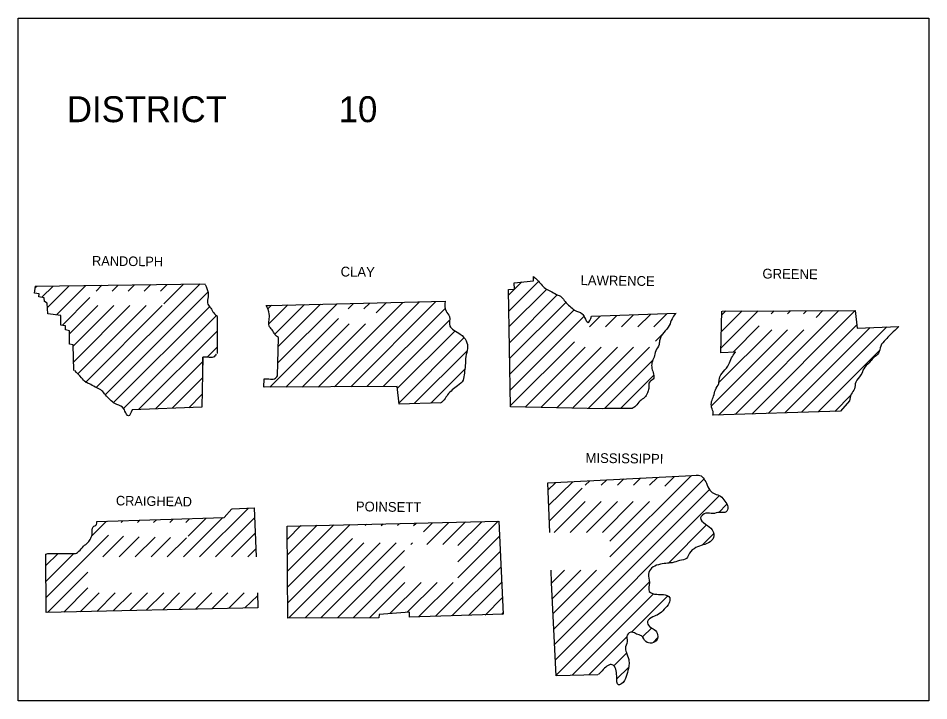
# Model space of a CAD drawing. Extents: x 21307 to 29830, y 1322443 to 1332359.
# Drawn here: x 27792.5 to 28192.5, y 1325389.6 to 1325689.6 of the extents above; entities that cross this region are included whole.
import ezdxf

# ---------------------------------------------------------------- set-up
doc = ezdxf.new("R2010")
doc.units = 0
doc.layers.add('R_Draft', color=7, linetype='Continuous')

msp = doc.modelspace()

# ---------------------------------------------------------------- linework, layer by layer
at = {"layer": 'R_Draft'}
msp.add_lwpolyline([(27792.46, 1325389.62), (27792.46, 1325689.62), (28192.46, 1325689.62), (28192.46, 1325389.62)], close=True, dxfattribs=at)
for points in [[(28049.06, 1325517.92), (28008.76, 1325518.82), (28007.86, 1325570.42), (28010.46, 1325570.52), (28010.36, 1325573.32), (28018.86, 1325574.12), (28018.86, 1325576.12)], [(27799.96, 1325571.82), (27874.56, 1325572.92)], [(27805.36, 1325562.42), (27814.86, 1325572.02)], [(27809.26, 1325559.22), (27822.06, 1325572.02)], [(27826.76, 1325527.32), (27872.36, 1325572.82)], [(27826.76, 1325569.62), (27829.26, 1325572.22)], [(27833.76, 1325569.62), (27836.36, 1325572.32)], [(27840.76, 1325569.62), (27843.56, 1325572.42)], [(27847.86, 1325569.62), (27850.76, 1325572.52)], [(27854.96, 1325569.62), (27857.96, 1325572.62)], [(27856.46, 1325564.12), (27865.06, 1325572.72)], [(28007.86, 1325567.92), (28010.46, 1325570.52), (28013.66, 1325573.72)], [(28008.06, 1325561.02), (28020.96, 1325573.92)], [(27816.96, 1325534.72), (27816.56, 1325546.12), (27814.96, 1325546.42), (27815.06, 1325552.22), (27813.26, 1325552.72), (27813.26, 1325554.42), (27811.16, 1325554.72), (27811.16, 1325559.02), (27805.46, 1325559.62), (27805.16, 1325564.42), (27804.06, 1325565.12), (27803.86, 1325566.72), (27801.56, 1325567.22), (27801.66, 1325568.42), (27799.66, 1325568.72), (27800.06, 1325571.82)], [(27799.96, 1325571.22), (27800.66, 1325571.82)], [(27802.86, 1325567.02), (27807.76, 1325571.92)], [(27830.76, 1325524.22), (27875.76, 1325569.22)], [(28008.16, 1325554.12), (28024.46, 1325570.42)], [(28008.36, 1325547.12), (28029.16, 1325568.02)], [(27811.76, 1325554.62), (27823.86, 1325566.82)], [(27901.36, 1325563.42), (27902.36, 1325563.42), (27979.96, 1325565.22)], [(27906.56, 1325538.12), (27932.56, 1325564.12)], [(27924.26, 1325527.52), (27961.46, 1325564.72)], [(27931.46, 1325527.62), (27968.76, 1325564.92)], [(27937.36, 1325561.82), (27939.76, 1325564.22)], [(27938.56, 1325527.62), (27975.96, 1325565.12)], [(27944.36, 1325561.82), (27946.96, 1325564.42)], [(27949.76, 1325560.12), (27954.26, 1325564.62)], [(28008.46, 1325540.22), (28032.96, 1325564.72)], [(27815.06, 1325550.92), (27827.46, 1325563.32)], [(27816.66, 1325545.52), (27834.46, 1325563.32)], [(27816.86, 1325538.62), (27841.56, 1325563.32)], [(27818.76, 1325533.42), (27848.66, 1325563.32)], [(27822.06, 1325529.62), (27822.16, 1325529.72), (27855.76, 1325563.32)], [(27834.46, 1325520.82), (27876.46, 1325562.82)], [(27902.06, 1325561.82), (27903.66, 1325563.52)], [(27902.66, 1325555.42), (27910.86, 1325563.62)], [(27905.16, 1325550.82), (27918.16, 1325563.82)], [(27906.66, 1325545.32), (27925.26, 1325563.92)], [(27945.66, 1325527.72), (27980.16, 1325562.22)], [(28008.56, 1325533.32), (28036.66, 1325561.42)], [(28101.16, 1325544.62), (28117.56, 1325561.02)], [(28101.16, 1325542.62), (28101.56, 1325560.92)], [(28101.36, 1325551.92), (28110.46, 1325561.02)], [(28101.56, 1325559.22), (28103.36, 1325561.02)], [(28101.66, 1325560.92), (28160.16, 1325561.22), (28160.96, 1325553.42), (28179.26, 1325554.12)], [(28107.36, 1325515.42), (28152.96, 1325561.12)], [(28114.66, 1325515.62), (28160.16, 1325561.22)], [(28123.26, 1325559.62), (28124.56, 1325561.02)], [(28130.36, 1325559.62), (28131.76, 1325561.02)], [(28137.36, 1325559.62), (28138.76, 1325561.02)], [(28142.96, 1325558.12), (28145.96, 1325561.12)], [(27838.76, 1325518.12), (27879.56, 1325558.92)], [(27879.86, 1325558.52), (27879.86, 1325542.22)], [(27903.06, 1325527.52), (27933.16, 1325557.62)], [(27952.76, 1325527.72), (27981.76, 1325556.72)], [(28008.66, 1325526.32), (28040.96, 1325558.52)], [(28043.36, 1325553.92), (28048.16, 1325558.72)], [(28044.36, 1325558.62), (28081.46, 1325559.92)], [(28050.46, 1325553.92), (28055.46, 1325559.02)], [(28057.46, 1325553.92), (28062.76, 1325559.22)], [(28064.66, 1325553.92), (28070.16, 1325559.42)], [(28071.66, 1325553.92), (28077.46, 1325559.72)], [(27845.46, 1325517.72), (27879.86, 1325552.12)], [(27910.06, 1325527.52), (27937.86, 1325555.32)], [(27917.26, 1325527.52), (27945.06, 1325555.32)], [(27959.06, 1325527.02), (27984.26, 1325552.12)], [(28097.06, 1325519.32), (28130.46, 1325552.72)], [(28100.06, 1325515.22), (28137.56, 1325552.72)], [(28100.36, 1325529.72), (28123.46, 1325552.72)], [(28106.46, 1325542.82), (28117.96, 1325554.42)], [(28121.96, 1325515.92), (28160.76, 1325554.72)], [(28129.26, 1325516.12), (28166.76, 1325553.62)], [(28136.56, 1325516.42), (28174.06, 1325553.92)], [(27906.36, 1325532.42), (27906.76, 1325549.22)], [(27959.76, 1325520.62), (27988.26, 1325549.12)], [(28072.46, 1325547.72), (28075.66, 1325550.92)], [(27875.46, 1325540.62), (27879.86, 1325545.02)], [(28008.76, 1325519.42), (28036.76, 1325547.42)], [(28015.16, 1325518.62), (28041.56, 1325545.02)], [(28022.06, 1325518.52), (28048.56, 1325545.02)], [(28029.06, 1325518.42), (28055.76, 1325545.02)], [(28035.96, 1325518.22), (28062.76, 1325545.02)], [(28042.86, 1325518.12), (28069.76, 1325545.02)], [(27873.56, 1325536.92), (27873.56, 1325540.62), (27873.06, 1325518.62)], [(27966.46, 1325520.22), (27989.56, 1325543.32)], [(28107.66, 1325542.82), (28101.16, 1325542.62)], [(28143.86, 1325516.62), (28170.66, 1325543.42)], [(27852.76, 1325517.92), (27873.56, 1325538.72), (27873.56, 1325538.72)], [(28049.96, 1325518.12), (28071.06, 1325539.22)], [(27973.76, 1325520.42), (27988.66, 1325535.32)], [(28057.06, 1325518.12), (28071.56, 1325532.62)], [(27860.06, 1325518.22), (27873.36, 1325531.52)], [(27900.36, 1325527.42), (27900.46, 1325531.12)], [(27867.36, 1325518.42), (27873.16, 1325524.22)], [(27978.16, 1325520.62), (27959.76, 1325519.92), (27958.96, 1325527.72), (27900.46, 1325527.42)], [(28157.66, 1325521.52), (28153.66, 1325516.92), (28097.66, 1325515.12)], [(28151.16, 1325516.82), (28158.26, 1325523.92)], [(27873.06, 1325518.62), (27842.46, 1325517.52)], [(28062.16, 1325518.12), (28049.96, 1325518.12), (28049.06, 1325517.92)], [(28025.06, 1325485.42), (28091.36, 1325488.82)], [(28052.36, 1325452.82), (28088.16, 1325488.62)], [(28076.46, 1325483.92), (28080.76, 1325488.22)], [(28025.96, 1325463.62), (28025.06, 1325485.42)], [(28025.16, 1325482.22), (28028.56, 1325485.62)], [(28025.46, 1325475.42), (28036.06, 1325485.92)], [(28027.76, 1325421.12), (28093.56, 1325486.92), (28093.66, 1325487.02)], [(28041.56, 1325484.32), (28043.56, 1325486.32)], [(28048.56, 1325484.32), (28050.96, 1325486.72)], [(28055.66, 1325484.32), (28058.46, 1325487.12)], [(28062.76, 1325484.32), (28065.86, 1325487.52)], [(28069.76, 1325484.32), (28073.26, 1325487.82)], [(28025.76, 1325468.62), (28040.16, 1325483.02)], [(28028.06, 1325414.32), (28096.16, 1325482.42)], [(28027.86, 1325463.62), (28041.46, 1325477.22)], [(28028.46, 1325407.62), (28100.56, 1325479.82)], [(28034.96, 1325463.62), (28048.56, 1325477.22)], [(28042.06, 1325463.62), (28055.66, 1325477.22)], [(28049.06, 1325463.62), (28062.66, 1325477.22)], [(28052.36, 1325459.82), (28069.76, 1325477.22)], [(27826.96, 1325468.42), (27882.96, 1325470.22), (27886.26, 1325474.02)], [(27872.16, 1325452.82), (27893.56, 1325474.22)], [(27886.46, 1325473.92), (27896.06, 1325474.42)], [(27896.06, 1325474.42), (27896.96, 1325452.82)], [(28100.26, 1325472.32), (28103.66, 1325475.82)], [(27824.76, 1325462.12), (27831.26, 1325468.52)], [(27837.76, 1325468.02), (27838.46, 1325468.72)], [(27844.86, 1325468.02), (27845.76, 1325468.92)], [(27851.96, 1325468.02), (27853.16, 1325469.22)], [(27859.06, 1325468.02), (27860.46, 1325469.42)], [(27865.06, 1325452.82), (27882.36, 1325470.12)], [(27866.06, 1325468.02), (27867.66, 1325469.62)], [(27867.16, 1325462.02), (27875.06, 1325469.92)], [(27879.16, 1325452.82), (27896.16, 1325469.92)], [(27910.66, 1325466.42), (28003.56, 1325468.52)], [(27971.96, 1325458.32), (27981.66, 1325468.02)], [(27979.06, 1325458.32), (27988.96, 1325468.22)], [(27985.56, 1325450.72), (28003.36, 1325468.52)], [(27985.56, 1325457.82), (27996.16, 1325468.32)], [(28003.56, 1325468.52), (28005.56, 1325427.62)], [(27910.96, 1325425.92), (27910.66, 1325466.42)], [(27910.76, 1325453.72), (27923.86, 1325466.82)], [(27910.76, 1325460.72), (27916.56, 1325466.62)], [(27910.86, 1325446.72), (27931.06, 1325466.92)], [(27910.96, 1325439.72), (27938.26, 1325467.12)], [(27944.86, 1325466.62), (27945.46, 1325467.22)], [(27951.96, 1325466.62), (27952.76, 1325467.42)], [(27959.06, 1325466.62), (27959.96, 1325467.52)], [(27966.16, 1325466.62), (27967.26, 1325467.72)], [(27970.46, 1325463.82), (27974.46, 1325467.82)], [(28078.06, 1325450.12), (28094.76, 1325466.92)], [(27804.76, 1325435.02), (27832.16, 1325462.42)], [(27829.66, 1325452.82), (27838.76, 1325461.92)], [(27836.76, 1325452.82), (27845.66, 1325461.72)], [(27843.86, 1325452.82), (27852.56, 1325461.52)], [(27850.86, 1325452.82), (27859.36, 1325461.32)], [(27857.96, 1325452.82), (27866.36, 1325461.22)], [(27886.16, 1325452.82), (27896.46, 1325463.12)], [(27910.96, 1325432.72), (27939.26, 1325461.02)], [(27985.56, 1325443.72), (28003.86, 1325461.92)], [(28092.96, 1325458.02), (28097.96, 1325463.02)], [(27893.26, 1325452.82), (27896.66, 1325456.22)], [(27911.36, 1325426.02), (27944.36, 1325459.02)], [(27918.46, 1325426.02), (27951.46, 1325459.02)], [(27925.46, 1325426.02), (27958.56, 1325459.02)], [(27964.96, 1325458.32), (27965.66, 1325459.02)], [(27804.56, 1325454.12), (27805.46, 1325454.32), (27817.66, 1325454.32)], [(27804.76, 1325428.42), (27804.56, 1325454.12)], [(27804.66, 1325442.02), (27816.96, 1325454.32)], [(27804.66, 1325449.02), (27809.96, 1325454.32)], [(27932.66, 1325426.12), (27962.16, 1325455.62)], [(27975.76, 1325426.82), (28004.16, 1325455.22)], [(27939.66, 1325426.12), (27962.16, 1325448.62)], [(27982.96, 1325426.92), (28004.56, 1325448.52)], [(27805.26, 1325428.42), (27823.06, 1325446.22)], [(28028.76, 1325400.62), (28026.76, 1325441.52), (28026.56, 1325447.02)], [(28026.86, 1325441.42), (28032.46, 1325447.02)], [(28027.16, 1325434.62), (28039.56, 1325447.02)], [(28027.46, 1325427.92), (28046.56, 1325447.02)], [(27946.76, 1325426.12), (27962.36, 1325441.62)], [(27955.66, 1325427.92), (27969.46, 1325441.62)], [(27963.36, 1325428.52), (27976.46, 1325441.62)], [(27968.46, 1325426.62), (27983.56, 1325441.62)], [(27990.26, 1325427.12), (28004.86, 1325441.72)], [(28028.76, 1325400.82), (28069.66, 1325441.82)], [(27812.46, 1325428.62), (27823.06, 1325439.22)], [(27819.66, 1325428.72), (27828.06, 1325437.02)], [(27826.96, 1325428.92), (27835.06, 1325437.02)], [(27834.16, 1325429.12), (27842.16, 1325437.02)], [(27841.46, 1325429.32), (27849.26, 1325437.02)], [(27848.66, 1325429.42), (27856.36, 1325437.02)], [(27855.96, 1325429.62), (27863.36, 1325437.02)], [(27863.16, 1325429.82), (27870.36, 1325437.02)], [(27870.36, 1325429.92), (27877.46, 1325437.02)], [(27877.56, 1325430.02), (27884.56, 1325437.02)], [(27884.86, 1325430.22), (27891.66, 1325437.02)], [(27897.56, 1325437.02), (27897.76, 1325430.52)], [(28035.76, 1325400.82), (28071.56, 1325436.62)], [(27892.06, 1325430.42), (27897.56, 1325435.82)], [(27997.56, 1325427.32), (28005.16, 1325435.02)], [(28061.96, 1325419.92), (28077.76, 1325435.72)], [(27897.76, 1325430.52), (27804.76, 1325428.42)], [(28005.56, 1325427.62), (27964.36, 1325426.42), (27964.36, 1325428.52), (27950.96, 1325427.52), (27950.86, 1325426.12), (27910.96, 1325425.92)], [(28004.86, 1325427.52), (28005.56, 1325428.22)], [(28066.76, 1325417.72), (28070.86, 1325421.72)], [(28043.06, 1325401.02), (28059.96, 1325417.92)], [(28071.36, 1325415.22), (28073.36, 1325417.22)], [(28054.16, 1325405.02), (28059.76, 1325410.72)], [(28055.36, 1325399.22), (28060.66, 1325404.42)], [(28047.06, 1325401.02), (28028.76, 1325400.62)]]:
    msp.add_lwpolyline(points, dxfattribs=at)
for points in [[(28018.86, 1325576.12), (28022.16, 1325572.72), (28024.06, 1325570.82), (28026.26, 1325569.72), (28028.86, 1325568.22), (28031.16, 1325567.02), (28032.66, 1325565.12), (28034.76, 1325563.02), (28036.86, 1325561.32), (28040.16, 1325559.72), (28041.26, 1325558.02), (28042.76, 1325555.92), (28044.36, 1325558.62)], [(27874.56, 1325572.62), (27875.86, 1325569.12), (27875.76, 1325566.42), (27875.76, 1325563.92), (27877.06, 1325562.22), (27878.36, 1325560.12), (27880.06, 1325558.62)], [(27979.96, 1325565.22), (27980.46, 1325560.82), (27981.86, 1325558.52), (27982.06, 1325554.32), (27983.76, 1325552.52), (27986.66, 1325550.72), (27989.26, 1325547.82), (27989.86, 1325544.42), (27989.06, 1325540.92), (27988.86, 1325537.02), (27988.46, 1325533.62), (27987.86, 1325530.52), (27985.46, 1325528.02), (27983.16, 1325526.22), (27981.06, 1325524.12), (27979.56, 1325521.92), (27977.96, 1325520.42)], [(27979.96, 1325565.22), (27980.46, 1325560.82), (27981.86, 1325558.52), (27982.06, 1325554.32), (27983.76, 1325552.52), (27986.66, 1325550.72), (27989.26, 1325547.82), (27989.86, 1325544.42), (27989.06, 1325540.92), (27988.86, 1325537.02), (27988.46, 1325533.62), (27987.86, 1325530.52), (27985.46, 1325528.02), (27983.16, 1325526.22), (27981.06, 1325524.12), (27979.56, 1325521.92), (27977.96, 1325520.42)], [(27906.76, 1325549.22), (27905.26, 1325550.62), (27903.96, 1325552.72), (27902.66, 1325554.42), (27902.66, 1325556.92), (27902.76, 1325559.62), (27901.36, 1325563.42)], [(28081.16, 1325559.82), (28079.66, 1325557.42), (28078.46, 1325554.62), (28076.06, 1325551.42), (28074.26, 1325548.32), (28073.96, 1325546.22), (28072.56, 1325543.42), (28071.76, 1325540.62), (28070.86, 1325538.22), (28070.86, 1325535.72), (28071.56, 1325533.22), (28071.36, 1325530.92), (28069.86, 1325529.82), (28069.46, 1325526.92), (28068.86, 1325524.92), (28067.56, 1325522.92), (28065.66, 1325521.42), (28063.66, 1325519.12), (28062.16, 1325518.12)], [(28179.26, 1325554.12), (28178.16, 1325553.02), (28175.56, 1325550.52), (28173.46, 1325548.32), (28171.36, 1325545.52), (28170.36, 1325542.42), (28168.06, 1325540.22), (28166.26, 1325538.22), (28163.86, 1325535.52), (28162.66, 1325532.82), (28160.36, 1325529.72), (28159.86, 1325526.72), (28158.36, 1325524.32), (28157.66, 1325521.52)], [(28179.26, 1325554.12), (28178.16, 1325553.02), (28175.56, 1325550.52), (28173.46, 1325548.32), (28171.36, 1325545.52), (28170.36, 1325542.42), (28168.06, 1325540.22), (28166.26, 1325538.22), (28163.86, 1325535.52), (28162.66, 1325532.82), (28160.36, 1325529.72), (28159.86, 1325526.72), (28158.36, 1325524.32), (28157.66, 1325521.52)], [(27879.46, 1325541.92), (27878.16, 1325540.62), (27875.66, 1325540.62), (27873.56, 1325540.62)], [(28097.66, 1325515.12), (28097.76, 1325516.12), (28097.06, 1325518.62), (28097.06, 1325521.12), (28097.96, 1325523.52), (28098.76, 1325526.32), (28100.16, 1325529.12), (28100.46, 1325531.22), (28102.26, 1325534.32), (28104.66, 1325537.52), (28105.86, 1325540.32), (28107.36, 1325542.72)], [(27842.46, 1325517.52), (27840.86, 1325514.82), (27839.36, 1325516.92), (27838.26, 1325518.62), (27834.96, 1325520.22), (27832.86, 1325521.92), (27830.76, 1325524.02), (27829.26, 1325525.92), (27826.96, 1325527.12), (27824.36, 1325528.62), (27822.16, 1325529.72), (27820.26, 1325531.62), (27817.36, 1325534.72)], [(27900.46, 1325531.12), (27902.56, 1325531.12), (27905.06, 1325531.12), (27906.36, 1325532.42)], [(28090.26, 1325488.72), (28091.36, 1325488.82), (28094.76, 1325485.22), (28096.26, 1325482.22), (28098.46, 1325480.52), (28100.96, 1325479.62), (28102.86, 1325477.32), (28104.16, 1325474.82), (28103.46, 1325472.62), (28100.66, 1325472.42), (28097.56, 1325471.92), (28094.56, 1325472.02), (28092.16, 1325470.02), (28094.36, 1325467.32), (28097.26, 1325464.82), (28098.06, 1325462.12), (28096.46, 1325459.52), (28093.26, 1325458.12), (28090.16, 1325456.92), (28087.36, 1325454.52), (28086.06, 1325452.22), (28082.96, 1325451.22), (28079.76, 1325450.32), (28076.96, 1325450.02), (28073.76, 1325449.42), (28070.66, 1325447.92), (28069.36, 1325445.32), (28069.76, 1325441.62), (28069.66, 1325437.72), (28072.96, 1325436.42), (28075.86, 1325436.32), (28078.66, 1325434.82), (28078.36, 1325432.62), (28076.26, 1325429.82), (28073.76, 1325427.62), (28071.26, 1325426.52), (28068.96, 1325424.42), (28069.76, 1325422.32), (28071.86, 1325420.92), (28073.36, 1325418.62), (28073.16, 1325416.52), (28070.76, 1325415.02), (28068.16, 1325415.62), (28066.26, 1325418.12), (28064.06, 1325418.92), (28062.16, 1325419.82), (28059.96, 1325418.52), (28059.96, 1325415.62), (28059.16, 1325412.52), (28059.86, 1325410.22), (28060.76, 1325407.02), (28060.66, 1325404.62), (28059.86, 1325401.22), (28058.16, 1325397.72), (28056.16, 1325396.62), (28055.36, 1325400.42), (28054.96, 1325403.52), (28053.76, 1325405.32), (28052.16, 1325405.42), (28050.06, 1325403.92), (28047.76, 1325401.62), (28047.16, 1325401.12)], [(28090.26, 1325488.72), (28091.36, 1325488.82), (28094.76, 1325485.22), (28096.26, 1325482.22), (28098.46, 1325480.52), (28100.96, 1325479.62), (28102.86, 1325477.32), (28104.16, 1325474.82), (28103.46, 1325472.62), (28100.66, 1325472.42), (28097.56, 1325471.92), (28094.56, 1325472.02), (28092.16, 1325470.02), (28094.36, 1325467.32), (28097.26, 1325464.82), (28098.06, 1325462.12), (28096.46, 1325459.52), (28093.26, 1325458.12), (28090.16, 1325456.92), (28087.36, 1325454.52), (28086.06, 1325452.22), (28082.96, 1325451.22), (28079.76, 1325450.32), (28076.96, 1325450.02), (28073.76, 1325449.42), (28070.66, 1325447.92), (28069.36, 1325445.32), (28069.76, 1325441.62), (28069.66, 1325437.72), (28072.96, 1325436.42), (28075.86, 1325436.32), (28078.66, 1325434.82), (28078.36, 1325432.62), (28076.26, 1325429.82), (28073.76, 1325427.62), (28071.26, 1325426.52), (28068.96, 1325424.42), (28069.76, 1325422.32), (28071.86, 1325420.92), (28073.36, 1325418.62), (28073.16, 1325416.52), (28070.76, 1325415.02), (28068.16, 1325415.62), (28066.26, 1325418.12), (28064.06, 1325418.92), (28062.16, 1325419.82), (28059.96, 1325418.52), (28059.96, 1325415.62), (28059.16, 1325412.52), (28059.86, 1325410.22), (28060.76, 1325407.02), (28060.66, 1325404.62), (28059.86, 1325401.22), (28058.16, 1325397.72), (28056.16, 1325396.62), (28055.36, 1325400.42), (28054.96, 1325403.52), (28053.76, 1325405.32), (28052.16, 1325405.42), (28050.06, 1325403.92), (28047.76, 1325401.62), (28047.16, 1325401.12)], [(27817.66, 1325454.32), (27819.16, 1325455.32), (27821.16, 1325457.62), (27823.06, 1325459.12), (27824.36, 1325461.12), (27824.96, 1325463.12), (27825.36, 1325466.02), (27826.86, 1325467.12), (27826.96, 1325468.42)]]:
    msp.add_spline(points, degree=3, dxfattribs=at)

# ---------------------------------------------------------------- texts
for s, p in [('DISTRICT', (27813.86, 1325643.92)), ('10', (27933.26, 1325643.92))]:
    msp.add_text(s, height=11.4, dxfattribs=at).set_placement(p)
for s, height, rotation, p in [('RANDOLPH', 4.201, 359.2583, (27824.86, 1325580.92)), ('CLAY', 4.3, 359.2258, (27934.06, 1325576.12)), ('LAWRENCE', 4.301, 359.2678, (28039.46, 1325572.32)), ('GREENE', 4.301, 359.2361, (28119.36, 1325575.22)), ('MISSISSIPPI', 4.2996, 359.3097, (28041.66, 1325494.22)), ('CRAIGHEAD', 4.201, 359.1159, (27835.36, 1325475.52)), ('POINSETT', 4.3, 359.1987, (27940.76, 1325472.92))]:
    msp.add_text(s, height=height, rotation=rotation, dxfattribs=at).set_placement(p)

doc.saveas('drawing.dxf')
